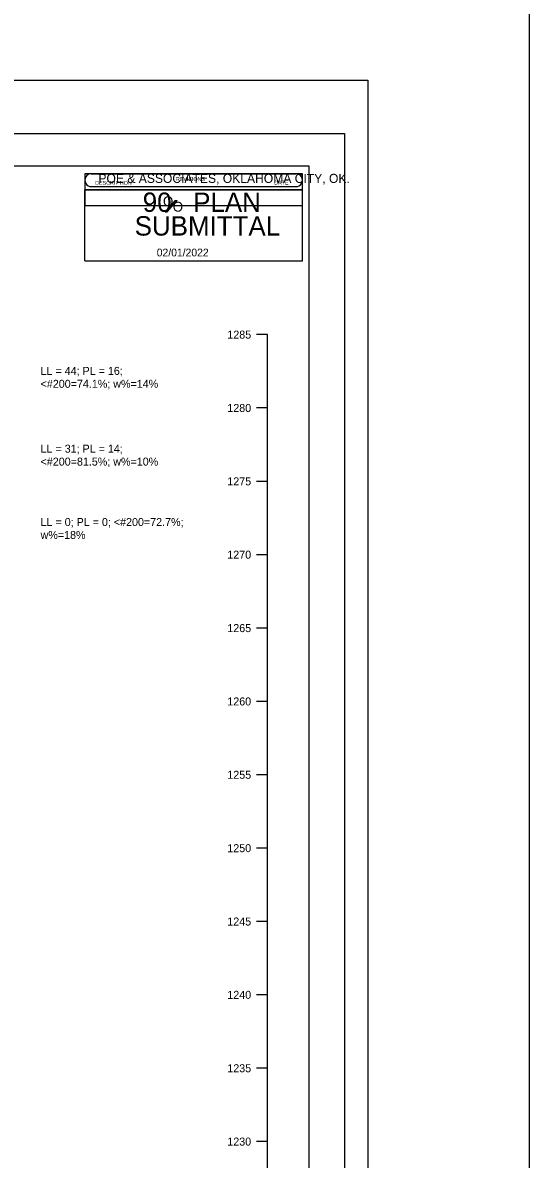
# Model space of a CAD drawing. Extents: x 2150161.5 to 2150203.1, y 143779.5 to 143868.5.
# Drawn here: x 2150195.23 to 2150203.07, y 143816.97 to 143834.58 of the extents above; entities that cross this region are included whole.
import ezdxf

# ---------------------------------------------------------------- set-up
doc = ezdxf.new("R2010")
doc.units = 0
for name, color, linetype in [('Default', 7, 'Continuous'), ('S', 7, 'Continuous'), ('SHT_Plot_Shape_Full', 7, 'Continuous'), ('SHT_Plot_Shape_Half', 7, 'Continuous'), ('SHT_Sheet_Border', 7, 'Continuous'), ('SHT_Stamp_90_Submit', 7, 'Continuous'), ('SHT_Stamp_Rev_Block', 7, 'Continuous')]:
    doc.layers.add(name, color=color, linetype=linetype)

msp = doc.modelspace()

# ---------------------------------------------------------------- linework, layer by layer
at = {"layer": 'Default'}
msp.add_line((2150199.018, 143816.11), (2150199.018, 143829.746), dxfattribs=at)
for points in [[(2150199.018, 143829.746), (2150198.851, 143829.746)], [(2150199.018, 143828.61), (2150198.851, 143828.61)], [(2150199.018, 143827.473), (2150198.851, 143827.473)], [(2150199.018, 143826.337), (2150198.851, 143826.337)], [(2150199.018, 143825.2), (2150198.851, 143825.2)], [(2150199.018, 143824.064), (2150198.851, 143824.064)], [(2150199.018, 143822.928), (2150198.851, 143822.928)], [(2150199.018, 143821.791), (2150198.851, 143821.791)], [(2150199.018, 143820.655), (2150198.851, 143820.655)], [(2150199.018, 143819.519), (2150198.851, 143819.519)], [(2150199.018, 143818.382), (2150198.851, 143818.382)], [(2150199.018, 143817.246), (2150198.851, 143817.246)]]:
    msp.add_lwpolyline(points, dxfattribs=at)
at = {"layer": 'S'}
msp.add_lwpolyline([(2150161.53, 143868.477), (2150203.071, 143868.477), (2150203.071, 143779.536), (2150161.53, 143779.536)], close=True, dxfattribs=at)
at = {"layer": 'SHT_Plot_Shape_Full'}
msp.add_lwpolyline([(2150164.575, 143833.688), (2150200.575, 143833.688), (2150200.575, 143809.688), (2150164.575, 143809.688)], close=True, dxfattribs=at)
at = {"layer": 'SHT_Plot_Shape_Half'}
msp.add_lwpolyline([(2150166.212, 143832.863), (2150200.212, 143832.863), (2150200.212, 143810.863), (2150166.212, 143810.863)], close=True, dxfattribs=at)
at = {"layer": 'SHT_Sheet_Border'}
msp.add_lwpolyline([(2150199.662, 143811.363), (2150168.162, 143811.363), (2150168.162, 143832.363), (2150199.662, 143832.363)], close=True, dxfattribs=at)
at = {"layer": 'SHT_Stamp_90_Submit'}
for p, q in [((2150196.293, 143832.239), (2150199.459, 143832.239)), ((2150196.193, 143831.989), (2150199.559, 143831.989)), ((2150196.193, 143830.889), (2150196.193, 143831.989)), ((2150196.293, 143832.039), (2150199.459, 143832.039)), ((2150199.559, 143830.889), (2150199.559, 143831.989)), ((2150197.437, 143831.65), (2150197.592, 143831.823)), ((2150197.454, 143831.65), (2150197.61, 143831.823)), ((2150197.459, 143831.65), (2150197.615, 143831.823)), ((2150197.467, 143831.65), (2150197.623, 143831.823)), ((2150197.592, 143831.823), (2150197.623, 143831.823)), ((2150197.437, 143831.65), (2150197.467, 143831.65)), ((2150196.193, 143830.889), (2150199.559, 143830.889))]:
    msp.add_line(p, q, dxfattribs=at)
for centre, start, end in [((2150196.294, 143832.139), 89.9952, 270), ((2150199.46, 143832.139), 270, 90.0048)]:
    msp.add_arc(centre, 0.1, start, end, dxfattribs=at)
at = {"layer": 'SHT_Stamp_Rev_Block'}
for p, q in [((2150196.194, 143832.239), (2150196.194, 143831.739)), ((2150199.559, 143832.239), (2150196.194, 143832.239)), ((2150199.559, 143831.739), (2150199.559, 143832.239)), ((2150199.559, 143831.989), (2150196.194, 143831.989)), ((2150199.559, 143831.739), (2150196.194, 143831.739))]:
    msp.add_line(p, q, dxfattribs=at)

# ---------------------------------------------------------------- texts
at = {"layer": 'Default'}
for s, p in [('1285', (2150198.398, 143829.684)), ('LL = 44; PL = 16;', (2150195.508, 143829.122)), ('<#200=74.1%; w%=14%', (2150195.508, 143828.922)), ('1280', (2150198.398, 143828.548)), ('LL = 31; PL = 14;', (2150195.508, 143827.917)), ('<#200=81.5%; w%=10%', (2150195.508, 143827.717)), ('1275', (2150198.398, 143827.411)), ('LL = 0; PL = 0; <#200=72.7%;', (2150195.508, 143826.781)), ('w%=18%', (2150195.508, 143826.581)), ('1270', (2150198.398, 143826.275)), ('1265', (2150198.398, 143825.138)), ('1260', (2150198.398, 143824.002)), ('1255', (2150198.398, 143822.866)), ('1250', (2150198.398, 143821.729)), ('1245', (2150198.398, 143820.593)), ('1240', (2150198.398, 143819.457)), ('1235', (2150198.398, 143818.32)), ('1230', (2150198.398, 143817.184))]:
    msp.add_text(s, height=0.124, dxfattribs=at).set_placement(p)
at = {"layer": 'SHT_Stamp_90_Submit'}
for s, height, p in [('POE & ASSOCIATES, OKLAHOMA CITY, OK.', 0.14, (2150196.403, 143832.096)), ('90   PLAN', 0.3, (2150197.089, 143831.647)), ('O', 0.153, (2150197.402, 143831.735)), ('O', 0.153, (2150197.554, 143831.651)), ('SUBMITTAL', 0.3, (2150196.964, 143831.28)), ('02/01/2022', 0.12, (2150197.306, 143830.958))]:
    msp.add_text(s, height=height, dxfattribs=at).set_placement(p)
at = {"layer": 'SHT_Stamp_Rev_Block'}
for s, height, p in [('DESCRIPTION', 0.05999, (2150196.353, 143832.067)), ('REVISIONS', 0.06, (2150197.602, 143832.126)), ('DATE', 0.06, (2150199.123, 143832.071))]:
    msp.add_text(s, height=height, dxfattribs=at).set_placement(p)

doc.saveas('drawing.dxf')
